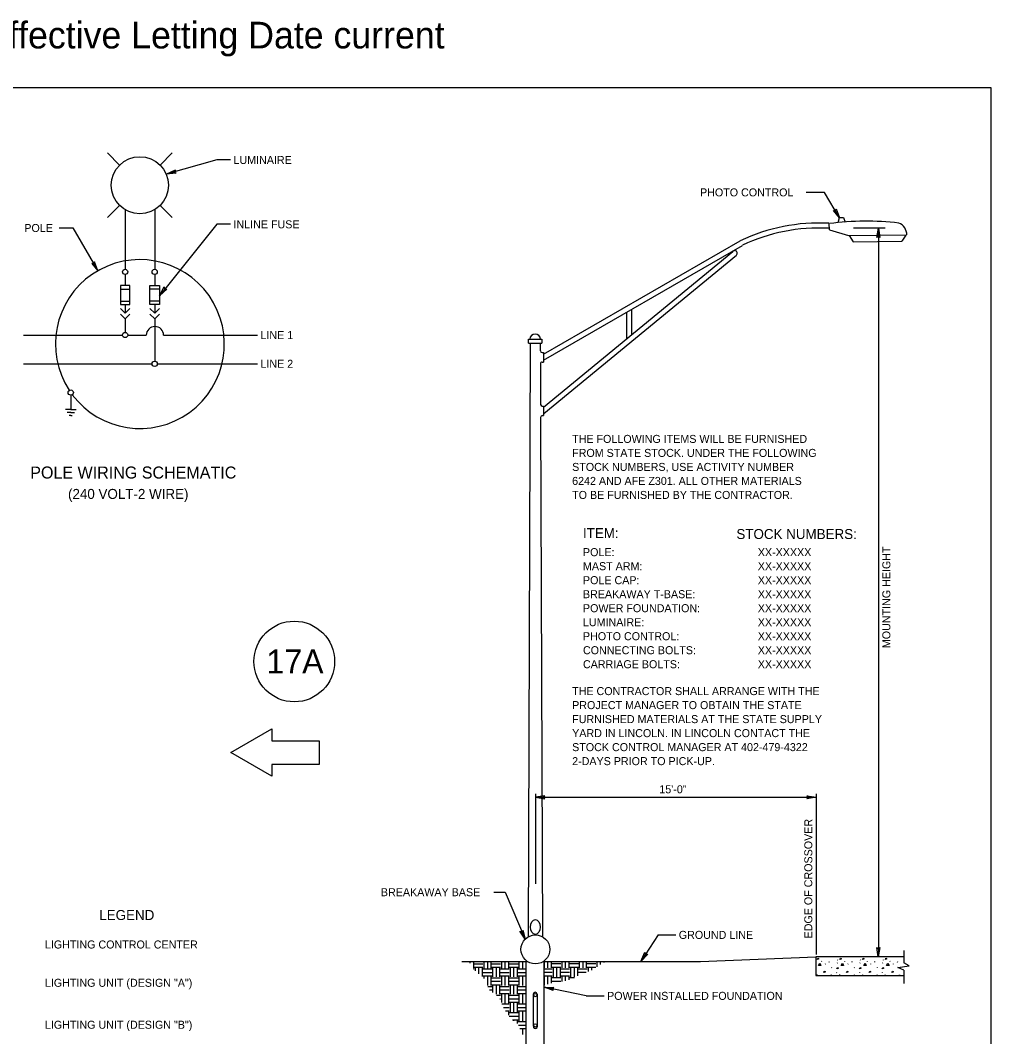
# Model space of a CAD drawing. Extents: x 99968 to 128667, y 90163 to 102182.
# Drawn here: x 122113 to 123567, y 94248 to 95772 of the extents above; entities that cross this region are included whole.
import ezdxf

# ---------------------------------------------------------------- set-up
doc = ezdxf.new("R2010")
doc.units = 0
for name, color, linetype in [('Border Prelim Stamp', 7, 'Continuous'), ('Default', 7, 'Continuous'), ('RD Standard Plans Active', 7, 'Continuous')]:
    doc.layers.add(name, color=color, linetype=linetype)

msp = doc.modelspace()

# ---------------------------------------------------------------- linework, layer by layer
at = {"layer": 'Border Prelim Stamp'}
msp.add_lwpolyline([(122428.1, 94674.2), (122489.6, 94709.7), (122489.6, 94692), (122560.5, 94692), (122560.5, 94656.5), (122489.6, 94656.5), (122489.6, 94638.8)], close=True, dxfattribs=at)
msp.add_ellipse((122523.3, 94810.9), major_axis=(-60.5, 0), ratio=0.999984, dxfattribs=at)
at = {"layer": 'Default'}
msp.add_lwpolyline([(120367.5, 95671.5), (123567.2, 95671.5), (123567.2, 93471.9), (120367.5, 93471.9)], close=True, dxfattribs=at)
at = {"layer": 'RD Standard Plans Active'}
for p, q in [((122261.5, 95555.2), (122243.5, 95573.3)), ((122322.1, 95555.2), (122340.1, 95573.3)), ((122407.1, 95562.8), (122331.3, 95541.5)), ((122427.7, 95562.8), (122407.1, 95562.8)), ((123318.1, 95514.2), (123290.6, 95514.2)), ((123340.8, 95476.1), (123318.1, 95514.2)), ((122243.5, 95476.6), (122261.5, 95494.7)), ((122340.1, 95476.6), (122322.1, 95494.7)), ((122269.7, 95488.3), (122269.7, 95399)), ((122314, 95488.3), (122314, 95399)), ((122407.1, 95466.3), (122321.1, 95359.3)), ((122427.7, 95466.3), (122407.1, 95466.3)), ((123325.4, 95458.1), (123325.3, 95467.3)), ((123338.8, 95469.1), (123340.4, 95476.6)), ((123340.4, 95476.6), (123346.7, 95476.6)), ((123346.7, 95476.6), (123349.1, 95469.4)), ((122170.6, 95460.8), (122191.1, 95460.8)), ((122191.1, 95460.8), (122229, 95396.6)), ((123325.4, 95458.1), (123353.9, 95449.6)), ((123353.9, 95449.6), (123441.2, 95450.4)), ((123355.1, 95449.4), (123360.9, 95440.2)), ((123409.2, 95460.5), (123361.6, 95460.5)), ((123398.8, 95460.5), (123398.8, 94368.2)), ((123440, 95450), (123434.2, 95440.9)), ((122896.9, 95271.4), (123191.8, 95441.6)), ((122896.9, 95262.6), (123195.2, 95434.8)), ((123360.9, 95440.2), (123434.2, 95440.9)), ((122897.1, 95192.1), (123180.7, 95425.7)), ((122897.5, 95182.5), (123186.1, 95420.3)), ((122269.7, 95391), (122269.7, 95374.5)), ((122314, 95391), (122314, 95374.5)), ((122262.6, 95369.1), (122276.8, 95369.1)), ((122321.1, 95369.1), (122306.9, 95369.1)), ((122262.6, 95351.1), (122276.8, 95351.1)), ((122269.7, 95346), (122269.7, 95333.2)), ((122321.1, 95351.1), (122306.9, 95351.1)), ((122314, 95346), (122314, 95333.2)), ((123021.7, 95294.7), (123021.7, 95334.6)), ((123029.3, 95300.9), (123029.3, 95339)), ((122269.7, 95324.7), (122269.7, 95304.4)), ((122314, 95324.7), (122314, 95261.2)), ((122117.6, 95300.3), (122265.7, 95300.3)), ((122273.6, 95300.3), (122301.3, 95300.3)), ((122327.3, 95300.3), (122468.1, 95300.3)), ((122877, 95288.2), (122873.8, 94397.9)), ((122874.6, 95293.9), (122894.5, 95293.9)), ((122874.6, 95288.2), (122874.6, 95293.9)), ((122874.6, 95288.2), (122894.5, 95288.2)), ((122892.1, 95288.2), (122892.1, 95276.8)), ((122894.5, 95293.9), (122894.5, 95288.2)), ((122894.9, 95274), (122896.9, 95274)), ((122896.9, 95274), (122896.9, 95259.8)), ((122117.6, 95257.2), (122310, 95257.2)), ((122317.9, 95257.2), (122468.1, 95257.2)), ((122892.2, 95257.1), (122892.4, 95196.1)), ((122895, 95259.8), (122896.9, 95259.8)), ((122188.2, 95210.2), (122188.2, 95188.5)), ((122188.1, 95188.5), (122180.2, 95188.5)), ((122188.2, 95188.5), (122196.2, 95188.5)), ((122895.1, 95193.7), (122897.1, 95193.7)), ((122897.1, 95193.7), (122897.1, 95179.5)), ((122188.1, 95184.2), (122182.7, 95184.3)), ((122188.1, 95179.8), (122185.8, 95179.8)), ((122188.2, 95184.2), (122193.6, 95184.2)), ((122188.2, 95179.8), (122190.5, 95179.8)), ((122892.5, 95177.2), (122895.3, 94398.2)), ((122895.2, 95179.5), (122897.1, 95179.5)), ((122884.7, 94612.3), (122884.7, 94477.6)), ((123305.8, 94612.3), (123305.8, 94371.5)), ((122884.7, 94607.3), (123305.8, 94607.3)), ((122822.6, 94465), (122839.6, 94465)), ((122839.6, 94465), (122869.3, 94394.4)), ((123068.5, 94401), (123042.9, 94361.1)), ((123068.5, 94401), (123095.2, 94401)), ((123132.4, 94361.1), (123304.9, 94368.2)), ((123304.9, 94368.2), (123304.9, 94339.9)), ((123435.8, 94368.2), (123304.9, 94368.2)), ((123436.8, 94377.5), (123436.8, 94359.3)), ((122774.4, 94361.1), (122872.8, 94361.1)), ((122786.4, 94360.7), (122786.4, 94358.4)), ((122791.7, 94360.7), (122791.7, 94351.1)), ((122792.9, 94357.8), (122806.1, 94357.8)), ((122792.9, 94352.6), (122806.1, 94352.6)), ((122794.2, 94351.2), (122794.2, 94347)), ((122799.5, 94351.2), (122799.5, 94342.8)), ((122804.7, 94351.2), (122804.7, 94338.6)), ((122807.5, 94360.7), (122807.5, 94351.1)), ((122812.7, 94360.7), (122812.7, 94351.1)), ((122818, 94360.7), (122818, 94351.1)), ((122819.2, 94357.8), (122832.4, 94357.8)), ((122819.2, 94352.6), (122832.4, 94352.6)), ((122820.5, 94351.2), (122820.5, 94338.1)), ((122825.8, 94351.2), (122825.8, 94338.1)), ((122831, 94351.2), (122831, 94338.1)), ((122833.8, 94360.7), (122833.8, 94351.1)), ((122839, 94360.7), (122839, 94351.1)), ((122844.3, 94360.7), (122844.3, 94351.1)), ((122845.5, 94357.8), (122858.7, 94357.8)), ((122845.5, 94352.6), (122858.7, 94352.6)), ((122846.8, 94351.2), (122846.8, 94338.1)), ((122852.1, 94351.2), (122852.1, 94338.1)), ((122857.3, 94351.2), (122857.3, 94338.1)), ((122860.1, 94360.7), (122860.1, 94351.1)), ((122865.3, 94360.8), (122865.3, 94351.1)), ((122870.6, 94360.8), (122870.6, 94351.1)), ((122871.1, 94177.7), (122871.1, 94360.8)), ((122897.6, 94361.1), (123132.4, 94361.1)), ((122897.8, 94293.8), (122897.8, 94360.8)), ((122897.8, 94165), (122897.8, 94360.8)), ((122897.9, 94360.8), (122897.9, 94351.4)), ((122903.1, 94360.8), (122903.1, 94351.4)), ((122908.4, 94360.8), (122908.4, 94351.4)), ((122909.7, 94357.9), (122922.8, 94357.9)), ((122909.7, 94352.7), (122922.8, 94352.7)), ((122911.1, 94351.3), (122911.1, 94338.2)), ((122916.4, 94351.3), (122916.4, 94338.2)), ((122921.6, 94351.3), (122921.6, 94338.2)), ((122924.2, 94360.8), (122924.2, 94351.4)), ((122929.4, 94360.8), (122929.4, 94351.4)), ((122934.7, 94360.8), (122934.7, 94351.4)), ((122936, 94357.9), (122949.1, 94357.9)), ((122936, 94352.7), (122949.1, 94352.7)), ((122937.4, 94351.3), (122937.4, 94338.2)), ((122942.7, 94351.3), (122942.7, 94338.2)), ((122947.9, 94351.3), (122947.9, 94339.7)), ((122950.5, 94360.8), (122950.5, 94351.4)), ((122955.7, 94360.8), (122955.7, 94351.4)), ((122961, 94360.8), (122961, 94351.4)), ((122962.3, 94357.9), (122975.4, 94357.9)), ((122962.3, 94352.7), (122975.4, 94352.7)), ((122963.7, 94351.3), (122963.7, 94345.9)), ((122969, 94351.3), (122969, 94348.2)), ((122976.8, 94360.8), (122976.8, 94353.1)), ((122982, 94360.8), (122982, 94356.4)), ((122987.3, 94360.8), (122987.3, 94359.8)), ((123313.8, 94361.7), (123314.1, 94361.3)), ((123319.2, 94356.9), (123319.5, 94357.6)), ((123325.3, 94360.3), (123325.6, 94360.9)), ((123328.6, 94352.1), (123328.9, 94351.6)), ((123337.1, 94358.6), (123337.4, 94359.3)), ((123337.7, 94363.7), (123338, 94363.2)), ((123347.9, 94361.7), (123348.2, 94361.3)), ((123353.2, 94356.9), (123353.5, 94357.6)), ((123359.4, 94360.3), (123359.7, 94360.9)), ((123362.7, 94352.1), (123363, 94351.6)), ((123371.2, 94358.6), (123371.5, 94359.3)), ((123371.7, 94363.7), (123372, 94363.2)), ((123381.9, 94361.7), (123382.2, 94361.3)), ((123387.3, 94356.9), (123387.6, 94357.6)), ((123393.4, 94360.3), (123393.7, 94360.9)), ((123396.8, 94352.1), (123397.1, 94351.6)), ((123405.2, 94358.6), (123405.5, 94359.3)), ((123405.8, 94363.7), (123406.1, 94363.2)), ((123416, 94361.7), (123416.3, 94361.3)), ((123421.4, 94356.9), (123421.7, 94357.6)), ((123427.5, 94360.3), (123427.8, 94360.9)), ((123427.8, 94352.2), (123445.2, 94354.4)), ((123436.8, 94347.9), (123427.8, 94352.2)), ((123430.8, 94352.1), (123431.1, 94351.6)), ((123445.2, 94354.4), (123436.8, 94359.3)), ((122792, 94349.9), (122792.9, 94349.9)), ((122806.1, 94349.9), (122819.2, 94349.9)), ((122806.1, 94344.7), (122819.2, 94344.7)), ((122806.1, 94339.4), (122819.2, 94339.4)), ((122807.5, 94338.1), (122807.5, 94335.6)), ((122812.7, 94338.1), (122812.7, 94325.3)), ((122818, 94338.1), (122818, 94324.9)), ((122819.2, 94336.8), (122832.4, 94336.8)), ((122832.4, 94349.9), (122845.5, 94349.9)), ((122832.4, 94344.7), (122845.5, 94344.7)), ((122832.4, 94339.4), (122845.5, 94339.4)), ((122833.8, 94338.1), (122833.8, 94324.9)), ((122839, 94338.1), (122839, 94324.9)), ((122844.3, 94338.1), (122844.3, 94324.9)), ((122845.5, 94336.8), (122858.7, 94336.8)), ((122858.7, 94349.9), (122871.1, 94349.9)), ((122858.7, 94344.7), (122871.1, 94344.7)), ((122858.7, 94339.4), (122871.1, 94339.4)), ((122860.1, 94338.1), (122860.1, 94324.9)), ((122865.3, 94338.1), (122865.3, 94324.9)), ((122870.6, 94338.1), (122870.6, 94324.9)), ((122897.8, 94350.1), (122909.7, 94350.1)), ((122897.8, 94344.9), (122909.7, 94344.9)), ((122897.8, 94339.6), (122909.7, 94339.6)), ((122897.9, 94338.3), (122897.9, 94325.6)), ((122903.1, 94338.3), (122903.1, 94327)), ((122908.4, 94338.3), (122908.4, 94328.4)), ((122909.7, 94337), (122922.8, 94337)), ((122922.8, 94350.1), (122936, 94350.1)), ((122922.8, 94344.9), (122936, 94344.9)), ((122922.8, 94339.6), (122936, 94339.6)), ((122924.2, 94338.3), (122924.2, 94331.1)), ((122929.4, 94338.3), (122929.4, 94332.3)), ((122934.7, 94338.3), (122934.7, 94333.6)), ((122936, 94337), (122943.1, 94337)), ((122949.1, 94350.1), (122962.3, 94350.1)), ((122949.1, 94344.9), (122960.9, 94344.9)), ((123304.9, 94339.9), (123435.8, 94339.9)), ((123306.9, 94340.8), (123307.2, 94341.5)), ((123336.3, 94344.8), (123336.4, 94344.1)), ((123341, 94340.8), (123341.3, 94341.5)), ((123370.3, 94344.8), (123370.4, 94344.1)), ((123375.1, 94340.8), (123375.4, 94341.5)), ((123404.4, 94344.8), (123404.5, 94344.1)), ((123409.1, 94340.8), (123409.4, 94341.5)), ((123436.8, 94347.9), (123436.8, 94328.3)), ((122813.5, 94323.7), (122819.2, 94323.7)), ((122819.2, 94331.6), (122832.4, 94331.6)), ((122819.2, 94326.3), (122832.4, 94326.3)), ((122820.5, 94325), (122820.5, 94314.6)), ((122825.8, 94325), (122825.8, 94311.9)), ((122831, 94325), (122831, 94311.9)), ((122832.4, 94323.7), (122845.5, 94323.7)), ((122845.5, 94331.6), (122858.7, 94331.6)), ((122845.5, 94326.3), (122858.7, 94326.3)), ((122846.8, 94325), (122846.8, 94311.9)), ((122852.1, 94325), (122852.1, 94311.9)), ((122857.3, 94325), (122857.3, 94311.9)), ((122858.7, 94323.7), (122871.1, 94323.7)), ((122961, 94309.6), (122898, 94322.6)), ((122909.7, 94331.7), (122922.8, 94331.7)), ((122816, 94318.4), (122819.2, 94318.4)), ((122826.2, 94310.6), (122832.4, 94310.6)), ((122831.4, 94305.3), (122832.4, 94305.3)), ((122832.4, 94318.4), (122845.5, 94318.4)), ((122832.4, 94313.2), (122845.5, 94313.2)), ((122833.8, 94311.8), (122833.8, 94299.5)), ((122839, 94311.8), (122839, 94298.7)), ((122844.3, 94311.8), (122844.3, 94298.7)), ((122845.5, 94310.6), (122858.7, 94310.6)), ((122845.5, 94305.3), (122858.7, 94305.3)), ((122858.7, 94318.4), (122871.1, 94318.4)), ((122858.7, 94313.2), (122871.1, 94313.2)), ((122860.1, 94311.8), (122860.1, 94298.7)), ((122865.3, 94311.8), (122865.3, 94298.7)), ((122870.6, 94311.8), (122870.6, 94298.7)), ((122881.6, 94312.3), (122881.6, 94264)), ((122887.4, 94312.3), (122887.3, 94263.1)), ((122961, 94309.6), (122987.7, 94309.6)), ((122834.6, 94297.4), (122845.5, 94297.4)), ((122836.8, 94292.2), (122845.5, 94292.2)), ((122845.5, 94300.1), (122858.7, 94300.1)), ((122846.8, 94298.8), (122846.8, 94285.6)), ((122852.1, 94298.8), (122852.1, 94285.6)), ((122857.3, 94298.8), (122857.3, 94285.6)), ((122858.7, 94297.4), (122871.1, 94297.4)), ((122858.7, 94292.2), (122871.1, 94292.2)), ((122840, 94286.9), (122845.5, 94286.9)), ((122844.3, 94285.6), (122844.3, 94280.5)), ((122845.5, 94284.4), (122858.7, 94284.4)), ((122845.5, 94279.1), (122858.7, 94279.1)), ((122858.7, 94286.9), (122871.1, 94286.9)), ((122860.1, 94285.6), (122860.1, 94272.4)), ((122865.3, 94285.6), (122865.3, 94272.4)), ((122870.6, 94285.6), (122870.6, 94272.4)), ((122850.2, 94273.8), (122858.7, 94273.8)), ((122852.1, 94272.5), (122852.1, 94272.4)), ((122857.3, 94272.5), (122857.3, 94268.3)), ((122858.7, 94271.2), (122871.1, 94271.2)), ((122859.4, 94265.9), (122871.1, 94265.9)), ((122861.2, 94260.7), (122871.1, 94260.7)), ((122865.3, 94259.3), (122865.3, 94251.7)), ((122870.6, 94259.3), (122870.6, 94254.9))]:
    msp.add_line(p, q, dxfattribs=at)
for points in [[(122346.3, 95543.1), (122331.3, 95541.5), (122345, 95547.9), (122343.4, 95544.9)], [(123335.6, 95489.4), (123340.8, 95476.1), (123331.5, 95487), (123334.7, 95486.3)], [(123396.4, 95446.4), (123398.8, 95460.5), (123401.2, 95446.4), (123398.8, 95448.6)], [(122219.8, 95407.6), (122229, 95396.6), (122223.9, 95410), (122223, 95406.9)], [(122262.6, 95346), (122276.8, 95346), (122276.8, 95374.4), (122262.6, 95374.4)], [(122321.1, 95346), (122306.9, 95346), (122306.9, 95374.4), (122321.1, 95374.4)], [(122332.4, 95369.3), (122321.1, 95359.3), (122328.4, 95372.5), (122328.9, 95369.1)], [(122898.8, 94609.7), (122884.7, 94607.3), (122898.8, 94604.9), (122896.6, 94607.3)], [(123291.7, 94609.7), (123305.8, 94607.3), (123291.7, 94604.9), (123294, 94607.3)], [(122866, 94408.3), (122869.3, 94394.4), (122861.6, 94406.4), (122864.7, 94405.3)], [(123401, 94382.3), (123398.6, 94368.2), (123396.3, 94382.3), (123398.6, 94380.1)], [(123053.1, 94372.3), (123042.9, 94361.1), (123048.8, 94375), (123049.7, 94371.7)], [(122911.3, 94317.4), (122898, 94322.6), (122912.3, 94322.1), (122909.6, 94320.2)]]:
    msp.add_lwpolyline(points, close=True, dxfattribs=at)
for points in [[(122262.6, 95340.3), (122269.7, 95333.2), (122276.8, 95340.3)], [(122262.6, 95331.8), (122269.7, 95324.7), (122276.8, 95331.8)], [(122321.1, 95340.3), (122314, 95333.2), (122306.9, 95340.3)], [(122321.1, 95331.8), (122314, 95324.7), (122306.9, 95331.8)], [(123307.1, 94364.2), (123308, 94366.1), (123309.5, 94364.9), (123307.1, 94364.2)], [(123341.1, 94364.2), (123342.1, 94366.1), (123343.6, 94364.9), (123341.1, 94364.2)], [(123375.2, 94364.2), (123376.1, 94366.1), (123377.6, 94364.9), (123375.2, 94364.2)], [(123409.3, 94364.2), (123410.2, 94366.1), (123411.7, 94364.9), (123409.3, 94364.2)], [(123309, 94354.9), (123311, 94358.7), (123312.6, 94355.2), (123309.1, 94354.9)], [(123336.6, 94350.1), (123337.5, 94352), (123339, 94350.9), (123336.6, 94350.1)], [(123343, 94354.9), (123345.1, 94358.7), (123346.7, 94355.2), (123343.1, 94354.9)], [(123370.6, 94350.1), (123371.5, 94352), (123373.1, 94350.9), (123370.6, 94350.1)], [(123377.1, 94354.9), (123379.1, 94358.7), (123380.7, 94355.2), (123377.2, 94354.9)], [(123404.7, 94350.1), (123405.6, 94352), (123407.1, 94350.9), (123404.7, 94350.1)], [(123411.2, 94354.9), (123413.2, 94358.7), (123414.8, 94355.2), (123411.2, 94354.9)], [(123316.9, 94344.7), (123317.8, 94346.6), (123319.4, 94345.5), (123316.9, 94344.7)], [(123328, 94339.9), (123328.2, 94341.2), (123329.6, 94339.9)], [(123351, 94344.7), (123351.9, 94346.6), (123353.4, 94345.5), (123351, 94344.7)], [(123362.1, 94339.9), (123362.3, 94341.2), (123363.6, 94339.9)], [(123385.1, 94344.7), (123386, 94346.6), (123387.5, 94345.5), (123385.1, 94344.7)], [(123396.2, 94339.9), (123396.3, 94341.2), (123397.7, 94339.9)], [(123419.1, 94344.7), (123420, 94346.6), (123421.5, 94345.5), (123419.1, 94344.7)], [(123430.2, 94339.9), (123430.4, 94341.2), (123431.7, 94339.9)]]:
    msp.add_lwpolyline(points, dxfattribs=at)
for centre, radius in [((122291.8, 95524.9), 42.8), ((122269.7, 95395), 3.97), ((122314, 95395), 3.97), ((122269.7, 95300.4), 3.97), ((122314, 95257.2), 3.97), ((122188.2, 95214.1), 3.97), ((122884.7, 94379.3), 21.7), ((122884.6, 94310.8), 2.42), ((122884.6, 94265.3), 2.42)]:
    msp.add_circle(centre, radius, dxfattribs=at)
for centre, radius, start, end in [((123310.5, 95190.6), 277.7, 87.1355, 115.3083), ((123380.7, 95066.2), 404.9, 83.09, 97.858), ((123423.5, 95451.2), 17.9, 357.2598, 70.7948), ((123310.5, 95190.6), 270.2, 87.1355, 115.3083), ((123183.5, 95423.1), 3.78, 313.2723, 140.0862), ((122291.8, 95286.8), 126.6, 216.8263, 213.2275), ((122314.3, 95300.1), 13, 0, 180), ((122884.4, 95293.8), 7.96, 0, 179.1143), ((122894.9, 95276.8), 2.74, 180.2953, 270), ((122895, 95257.1), 2.74, 90, 180.3299), ((122895.1, 95196.4), 2.74, 180.2953, 270), ((122895.2, 95176.8), 2.74, 90, 180.3299), ((122884.5, 94312), 2.91, 6.8921, 173.1079), ((122884.5, 94263.5), 2.91, 171.4997, 6.8921)]:
    msp.add_arc(centre, radius, start, end, dxfattribs=at)
msp.add_ellipse((122884.7, 94412.8), major_axis=(0, 11.2), ratio=0.661267, dxfattribs=at)

# ---------------------------------------------------------------- texts
at = {"layer": 'Border Prelim Stamp'}
msp.add_text('17A', height=36, dxfattribs=at).set_placement((122481.5, 94792.9))
at = {"layer": 'RD Standard Plans Active'}
for s, height, p in [('Effective Letting Date current', 40, (122058.8, 95730)), (' LUMINAIRE', 12, (122427.7, 95556.8)), ('PHOTO CONTROL ', 12, (123131.5, 95508.2)), ('POLE ', 12, (122118.6, 95454.8)), (' INLINE FUSE', 12, (122427.7, 95460.3)), (' LINE 1', 12, (122468.1, 95294.3)), (' LINE 2', 12, (122468.1, 95251.2)), ('THE FOLLOWING ITEMS WILL BE FURNISHED', 12, (122939.8, 95138.6)), ('FROM STATE STOCK. UNDER THE FOLLOWING', 12, (122939.8, 95117.6)), ('POLE WIRING SCHEMATIC', 18, (122127.5, 95085.2)), ('STOCK NUMBERS, USE ACTIVITY NUMBER', 12, (122939.8, 95096.6)), ('6242 AND AFE Z301. ALL OTHER MATERIALS', 12, (122939.8, 95075.6)), ('(240 VOLT-2 WIRE)', 15, (122184.1, 95054.6)), ('TO BE FURNISHED BY THE CONTRACTOR.', 12, (122939.8, 95054.6)), ('ITEM:', 15, (122956, 94995.8)), ('STOCK NUMBERS:', 15, (123186, 94994.5)), ('POLE:', 12, (122956, 94968.8)), ('XX-XXXXX', 12, (123218.1, 94968.8)), ('MAST ARM:', 12, (122956, 94947.8)), ('XX-XXXXX', 12, (123218.1, 94947.8)), ('POLE CAP:', 12, (122956, 94926.8)), ('XX-XXXXX', 12, (123218.1, 94926.8)), ('BREAKAWAY T-BASE:', 12, (122956, 94905.8)), ('XX-XXXXX', 12, (123218.1, 94905.8)), ('POWER FOUNDATION:', 12, (122956, 94884.8)), ('XX-XXXXX', 12, (123218.1, 94884.8)), ('LUMINAIRE:', 12, (122956, 94863.8)), ('XX-XXXXX', 12, (123218.1, 94863.8)), ('PHOTO CONTROL:', 12, (122956, 94842.8)), ('XX-XXXXX', 12, (123218.1, 94842.8)), ('CONNECTING BOLTS:', 12, (122956, 94821.8)), ('XX-XXXXX', 12, (123218.1, 94821.8)), ('CARRIAGE BOLTS:', 12, (122956, 94800.8)), ('XX-XXXXX', 12, (123218.1, 94800.8)), ('THE CONTRACTOR SHALL ARRANGE WITH THE', 12, (122939.8, 94760.5)), ('PROJECT MANAGER TO OBTAIN THE STATE', 12, (122939.8, 94739.5)), ('FURNISHED MATERIALS AT THE STATE SUPPLY', 12, (122939.8, 94718.5)), ('YARD IN LINCOLN. IN LINCOLN CONTACT THE', 12, (122939.8, 94697.5)), ('STOCK CONTROL MANAGER AT 402-479-4322', 12, (122939.8, 94676.5)), ('2-DAYS PRIOR TO PICK-UP.', 12, (122939.8, 94655.5)), ('15\'-0"', 12, (123070.5, 94613.3)), ('BREAKAWAY BASE ', 12, (122653.1, 94459)), ('LEGEND', 15, (122231, 94423.3)), (' GROUND LINE', 12, (123095.2, 94395)), ('LIGHTING CONTROL CENTER', 12, (122149.5, 94380.6)), ('LIGHTING UNIT (DESIGN "A")', 12, (122149.5, 94323.2)), (' POWER INSTALLED FOUNDATION ', 12, (122987.7, 94303.6)), ('LIGHTING UNIT (DESIGN "B")', 12, (122149.5, 94260.3))]:
    msp.add_text(s, height=height, dxfattribs=at).set_placement(p)
for s, p in [('MOUNTING HEIGHT', (123416.8, 94830.9)), ('EDGE OF CROSSOVER', (123299.8, 94395.7))]:
    msp.add_text(s, height=12, rotation=90, dxfattribs=at).set_placement(p)

doc.saveas('drawing.dxf')
